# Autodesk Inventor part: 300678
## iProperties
Created: 2007-11
Part Number: 300678
Document SubType Name: Modeling
Designer: TH
Density: 7.85 g/cm^3
Mass: 505.093 g
Surface Area: 1294.91 cm^2
Volume: 64.343 cm^3
Material: Steel
Description: LOWER PAN
Component Category: Back Component
Author: TH
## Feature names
1. Extrusion1
2. Fillet1
3. Fillet2
4. Fillet3
5. Fillet4
6. Hole1
